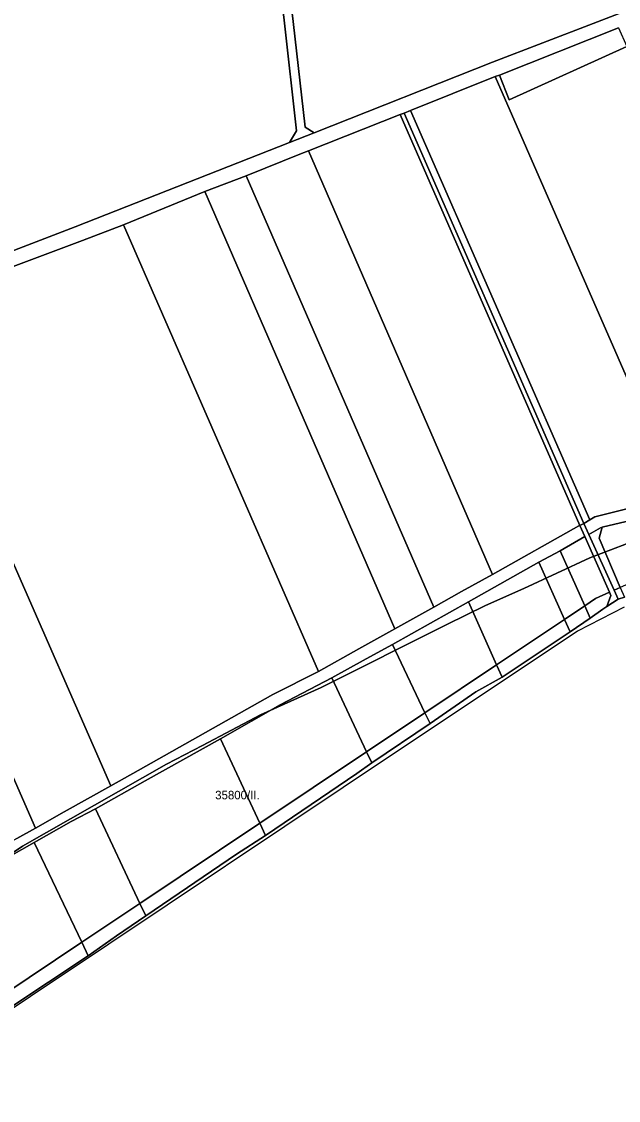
# Model space of a CAD drawing. Extents: x -541351 to -537540, y -1162694 to -1159725.
# Drawn here: x -540662 to -540312, y -1161835 to -1161203 of the extents above; entities that cross this region are included whole.
import ezdxf

# ---------------------------------------------------------------- set-up
doc = ezdxf.new("R2010")
doc.units = 0
for name, color, linetype in [('95560013', 7, 'Continuous'), ('95590013', 7, 'Continuous'), ('95610013', 7, 'Continuous'), ('95630013', 7, 'Continuous'), ('95640013', 7, 'Continuous'), ('95660013', 7, 'Continuous')]:
    doc.layers.add(name, color=color, linetype=linetype)

msp = doc.modelspace()

# ---------------------------------------------------------------- linework, layer by layer
at = {"layer": '95560013'}
for points in [[(-540504.91, -1161273.51), (-540500.7, -1161266.6), (-540508.04, -1161201.67), (-540518.17, -1161114.81), (-540521.81, -1161085.08), (-540526.03, -1161049.48), (-540529.8, -1161015.59), (-540525.02, -1161013.78), (-540520.88, -1161049.35), (-540513.36, -1161115.83), (-540511.17, -1161133.39), (-540502.72, -1161202.63), (-540495.73, -1161264.57), (-540490.48, -1161267.79)], [(-540316.41, -1161056.82), (-540301.95, -1161142.81), (-540294.21, -1161187.08), (-540297.43, -1161192.42), (-540386.02, -1161226.29), (-540490.48, -1161267.79), (-540495.73, -1161264.57), (-540502.72, -1161202.63), (-540511.17, -1161133.39), (-540413.71, -1161095.07)], [(-540725.06, -1161359.22), (-540729.41, -1161355.94), (-540729.28, -1161280.63), (-540729.47, -1161197.86), (-540518.17, -1161114.81), (-540508.04, -1161201.67), (-540500.7, -1161266.6), (-540504.91, -1161273.51), (-540630.42, -1161322.96), (-540718.49, -1161356.81)], [(-540376.08, -1161248.51), (-540307.23, -1161217.26), (-540200.82, -1161461.87), (-540222.72, -1161467.24), (-540276.94, -1161480.65), (-540384.28, -1161234.82), (-540381.86, -1161234.02)], [(-540326.01, -1161493), (-540328.96, -1161494.8), (-540433.89, -1161254.72), (-540384.28, -1161234.82), (-540276.94, -1161480.65)], [(-540440, -1161257.07), (-540334.69, -1161498.02), (-540335.38, -1161498.32), (-540385.94, -1161526.74), (-540493.77, -1161278.41)], [(-540404.1, -1161536.79), (-540420.29, -1161545.94), (-540530.17, -1161292.96), (-540497.91, -1161279.89), (-540493.77, -1161278.41), (-540385.94, -1161526.74)], [(-540554.44, -1161302.29), (-540530.17, -1161292.96), (-540420.29, -1161545.94), (-540443.15, -1161558.53)], [(-540443.15, -1161558.53), (-540464.14, -1161570.29), (-540487.95, -1161583.73), (-540602.06, -1161321.76), (-540554.44, -1161302.29)], [(-540626.04, -1161331.01), (-540602.06, -1161321.76), (-540487.95, -1161583.73), (-540514.53, -1161597.21), (-540593.57, -1161641.71), (-540609.41, -1161650.66), (-540731.05, -1161373.08), (-540722.92, -1161367.3), (-540714.45, -1161363.95)], [(-540772.43, -1161404.49), (-540731.05, -1161373.08), (-540609.41, -1161650.66), (-540636.75, -1161665.9), (-540653.69, -1161675.45)], [(-540799.44, -1161425.52), (-540785.62, -1161415.04), (-540782.43, -1161412.5), (-540772.43, -1161404.49), (-540653.69, -1161675.45), (-540664.54, -1161681.55), (-540667.99, -1161683.49), (-540707.7, -1161705.8), (-540822.56, -1161443.77)], [(-540326.01, -1161493), (-540276.94, -1161480.65), (-540222.72, -1161467.24), (-540200.82, -1161461.87), (-540125.75, -1161443.43), (-540108.57, -1161439.09), (-540092.67, -1161427.78), (-540090.07, -1161433.71), (-540096.62, -1161439.42), (-540120.26, -1161449.57), (-540220.01, -1161473.81), (-540240.99, -1161479.13), (-540307.68, -1161495.7), (-540321.68, -1161499.09), (-540322.64, -1161499.38), (-540329.57, -1161503.37), (-540332.4, -1161496.91), (-540328.96, -1161494.8)], [(-540329.57, -1161503.37), (-540322.64, -1161499.38), (-540321.68, -1161499.09), (-540323.5, -1161505.54), (-540311.08, -1161534.39), (-540314.73, -1161536.01)], [(-540293.97, -1161526.78), (-540311.08, -1161534.39), (-540323.5, -1161505.54), (-540321.68, -1161499.09), (-540307.68, -1161495.7)], [(-540317.37, -1161537.18), (-540325.54, -1161540.88), (-540331.95, -1161545.18), (-540346.4, -1161512.82), (-540331.84, -1161504.54)], [(-540358.74, -1161519.54), (-540346.4, -1161512.82), (-540331.95, -1161545.18), (-540343.73, -1161553.07)], [(-540383.56, -1161579.74), (-540425.5, -1161607.82), (-540444.46, -1161567.75), (-540399.99, -1161542.79)], [(-540444.46, -1161567.75), (-540425.5, -1161607.82), (-540459.69, -1161630.71), (-540480.02, -1161587.35), (-540460.02, -1161576.2)], [(-540545.21, -1161623.18), (-540510.22, -1161603.18), (-540480.02, -1161587.35), (-540459.69, -1161630.71), (-540522.27, -1161672.61)], [(-540589.38, -1161647.65), (-540545.21, -1161623.18), (-540522.27, -1161672.61), (-540592.43, -1161719.58), (-540618.58, -1161664.08)], [(-540632.69, -1161671.62), (-540618.58, -1161664.08), (-540592.43, -1161719.58), (-540626.51, -1161742.4), (-540654.37, -1161683.86)], [(-540672.85, -1161773.42), (-540702.46, -1161710.97), (-540654.37, -1161683.86), (-540626.51, -1161742.4)]]:
    msp.add_lwpolyline(points, close=True, dxfattribs=at)
msp.add_lwpolyline([(-540664.54, -1161681.55), (-540653.69, -1161675.45), (-540636.75, -1161665.9), (-540609.41, -1161650.66), (-540593.57, -1161641.71), (-540514.53, -1161597.21), (-540487.95, -1161583.73), (-540464.14, -1161570.29), (-540443.15, -1161558.53), (-540420.29, -1161545.94), (-540404.1, -1161536.79), (-540385.94, -1161526.74), (-540335.38, -1161498.32), (-540334.69, -1161498.02), (-540331.84, -1161504.54), (-540346.4, -1161512.82), (-540358.74, -1161519.54), (-540399.99, -1161542.79), (-540444.46, -1161567.75), (-540460.02, -1161576.2), (-540480.02, -1161587.35), (-540510.22, -1161603.18), (-540545.21, -1161623.18), (-540589.38, -1161647.65), (-540618.58, -1161664.08), (-540632.69, -1161671.62), (-540654.37, -1161683.86), (-540702.46, -1161710.97)], dxfattribs=at)
at = {"layer": '95590013'}
msp.add_lwpolyline([(-540312.06, -1161206.17), (-540307.23, -1161217.26), (-540376.08, -1161248.51), (-540381.86, -1161234.02)], close=True, dxfattribs=at)
at = {"layer": '95610013'}
msp.add_lwpolyline([(-540358.74, -1161519.54), (-540343.73, -1161553.07), (-540383.56, -1161579.74), (-540399.99, -1161542.79)], close=True, dxfattribs=at)
at = {"layer": '95630013'}
for points in [[(-540437.6, -1161256.21), (-540332.4, -1161496.91), (-540334.69, -1161498.02), (-540440, -1161257.07)], [(-540334.69, -1161498.02), (-540332.4, -1161496.91), (-540329.57, -1161503.37), (-540314.73, -1161536.01), (-540312.32, -1161541.31), (-540318.97, -1161545.6), (-540316.56, -1161539), (-540317.37, -1161537.18), (-540331.84, -1161504.54)]]:
    msp.add_lwpolyline(points, close=True, dxfattribs=at)
for points in [[(-540669.18, -1161781.14), (-540622.77, -1161750.26), (-540606.25, -1161738.63), (-540589.03, -1161726.79), (-540535.92, -1161690.81), (-540518.94, -1161679.77), (-540465.44, -1161643.47), (-540456.62, -1161637.24), (-540422.51, -1161614.13), (-540395.65, -1161595.59), (-540380.32, -1161587.03), (-540340.47, -1161560.36), (-540328.77, -1161552.31), (-540321.23, -1161547.02), (-540318.97, -1161545.6), (-540312.32, -1161541.31), (-540308.63, -1161540.09)], [(-540308.8, -1161545.84), (-540336.16, -1161560.05), (-540473.44, -1161651.74), (-540610.73, -1161743.43), (-540748.01, -1161835.11)]]:
    msp.add_lwpolyline(points, dxfattribs=at)
at = {"layer": '95640013'}
for points in [[(-540718.49, -1161356.81), (-540630.42, -1161322.96), (-540504.91, -1161273.51), (-540490.48, -1161267.79), (-540386.02, -1161226.29), (-540297.43, -1161192.42)], [(-540312.06, -1161206.17), (-540381.86, -1161234.02), (-540384.28, -1161234.82), (-540433.89, -1161254.72), (-540437.6, -1161256.21), (-540440, -1161257.07), (-540493.77, -1161278.41), (-540497.91, -1161279.89), (-540530.17, -1161292.96), (-540554.44, -1161302.29), (-540602.06, -1161321.76), (-540626.04, -1161331.01), (-540714.45, -1161363.95)]]:
    msp.add_lwpolyline(points, dxfattribs=at)
for points in [[(-540328.96, -1161494.8), (-540332.4, -1161496.91), (-540437.6, -1161256.21), (-540433.89, -1161254.72)], [(-540318.97, -1161545.6), (-540321.23, -1161547.02), (-540328.77, -1161552.31), (-540331.95, -1161545.18), (-540325.54, -1161540.88), (-540317.37, -1161537.18), (-540316.56, -1161539)], [(-540308.63, -1161540.09), (-540312.32, -1161541.31), (-540314.73, -1161536.01), (-540311.08, -1161534.39)], [(-540331.95, -1161545.18), (-540328.77, -1161552.31), (-540340.47, -1161560.36), (-540343.73, -1161553.07)], [(-540383.56, -1161579.74), (-540343.73, -1161553.07), (-540340.47, -1161560.36), (-540380.32, -1161587.03)], [(-540395.65, -1161595.59), (-540422.51, -1161614.13), (-540425.5, -1161607.82), (-540383.56, -1161579.74), (-540380.32, -1161587.03)], [(-540422.51, -1161614.13), (-540456.62, -1161637.24), (-540459.69, -1161630.71), (-540425.5, -1161607.82)], [(-540465.44, -1161643.47), (-540518.94, -1161679.77), (-540522.27, -1161672.61), (-540459.69, -1161630.71), (-540456.62, -1161637.24)], [(-540589.03, -1161726.79), (-540592.43, -1161719.58), (-540522.27, -1161672.61), (-540518.94, -1161679.77), (-540535.92, -1161690.81)], [(-540589.03, -1161726.79), (-540606.25, -1161738.63), (-540622.77, -1161750.26), (-540626.51, -1161742.4), (-540592.43, -1161719.58)], [(-540622.77, -1161750.26), (-540669.18, -1161781.14), (-540672.85, -1161773.42), (-540626.51, -1161742.4)]]:
    msp.add_lwpolyline(points, close=True, dxfattribs=at)
at = {"layer": '95660013'}
for points in [[(-540295.12, -1161504), (-540329, -1161517), (-540367.5, -1161535), (-540390.12, -1161545), (-540412.69, -1161556), (-540486.37, -1161593), (-540521.81, -1161609), (-540555.81, -1161627), (-540576.81, -1161638), (-540661.31, -1161686), (-540720.81, -1161726)], [(-540720.81, -1161726), (-540661.31, -1161686), (-540576.81, -1161638), (-540555.81, -1161627), (-540521.81, -1161609), (-540486.37, -1161593), (-540412.69, -1161556), (-540390.12, -1161545), (-540367.5, -1161535), (-540329, -1161517), (-540295.12, -1161504)], [(-540308.8, -1161545.84), (-540336.16, -1161560.05), (-540473.44, -1161651.74), (-540610.73, -1161743.43), (-540748.01, -1161835.11)]]:
    msp.add_lwpolyline(points, dxfattribs=at)

# ---------------------------------------------------------------- texts
msp.add_text('35800/II.', height=5, rotation=0, dxfattribs=at).set_placement((-540548.35, -1161658.58))

doc.saveas('drawing.dxf')
